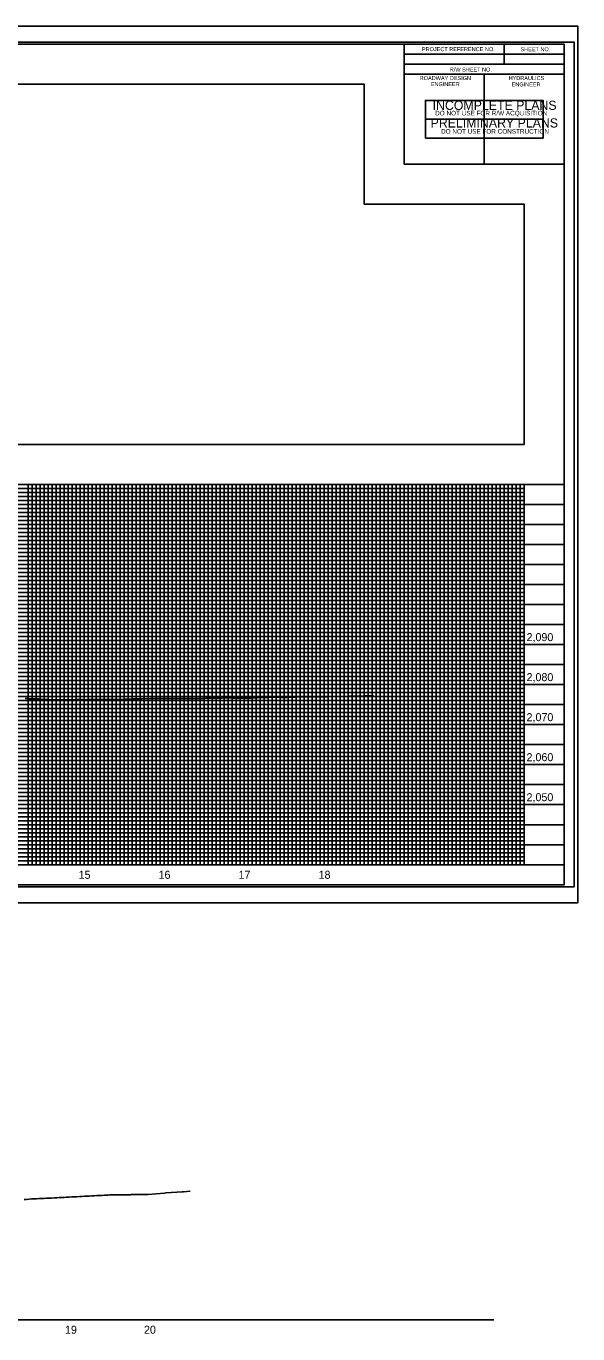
# Model space of a CAD drawing. Extents: x 757145 to 758829, y 592169 to 594973.
# Drawn here: x 758139 to 758829, y 592169 to 593803 of the extents above; entities that cross this region are included whole.
import ezdxf

# ---------------------------------------------------------------- set-up
doc = ezdxf.new("R2010")
doc.units = 0
for name, color, linetype in [('Exist CMT EOP', 7, 'Continuous'), ('Exist Vertical Profile Horizontal Axis Label Major', 7, 'Continuous'), ('Old_Level_63', 7, 'Continuous'), ('Prop CMT DNC', 7, 'Continuous'), ('Prop Dimension', 7, 'Continuous'), ('Scratch_Level_4', 7, 'Continuous'), ('Sheet Cutting Line CELL', 7, 'Continuous'), ('Sheet DOT Grid CELL', 7, 'Continuous'), ('Sheet Plan And Profile CELL', 7, 'Continuous'), ('Sheet Plot Border Inside CELL', 7, 'Continuous'), ('Sheet Plot Border Outside CELL', 7, 'Continuous'), ('Sheet Profile Grid Major CELL', 7, 'Continuous'), ('Sheet Profile Grid Middle CELL', 7, 'Continuous'), ('Sheet Profile Grid Minor CELL', 7, 'Continuous'), ('Sheet Sticker Incomplete CELL', 7, 'Continuous'), ('Sheet Sticker Preliminary CELL', 7, 'Continuous')]:
    doc.layers.add(name, color=color, linetype=linetype)

msp = doc.modelspace()

# ---------------------------------------------------------------- linework, layer by layer
at = {"layer": 'Exist CMT EOP'}
for points in [[(758138.3, 592962.9), (758139.9, 592962.9), (758140.2, 592962.9), (758141.4, 592962.8), (758143, 592962.7), (758144.5, 592962.6), (758146.1, 592962.5), (758147.6, 592962.3), (758149.1, 592962.3), (758150.7, 592962.3), (758152.2, 592962.3), (758153.8, 592962.3), (758154.5, 592962.3), (758155.3, 592962.2), (758156.9, 592962.1), (758158.4, 592961.9), (758160, 592961.8), (758161.5, 592961.7)], [(758161.5, 592961.7), (758161.9, 592961.6), (758163.1, 592961.6), (758164.6, 592961.6), (758165.3, 592961.6), (758166.2, 592961.6), (758167.7, 592961.5), (758169.2, 592961.4), (758170.3, 592961.4), (758170.8, 592961.4), (758172.3, 592961.4), (758173.9, 592961.4), (758175.4, 592961.3), (758177, 592961.3), (758178.5, 592961.3), (758180.1, 592961.3), (758181.6, 592961.3), (758183.2, 592961.3), (758184.7, 592961.3), (758186.3, 592961.3), (758187.8, 592961.3), (758189.3, 592961.3), (758190.9, 592961.3), (758191.8, 592961.3), (758192.4, 592961.3), (758194, 592961.4), (758195.5, 592961.4), (758197.1, 592961.4), (758197.5, 592961.4), (758198.6, 592961.4), (758200.2, 592961.5), (758201.2, 592961.5), (758201.7, 592961.5), (758203.3, 592961.5), (758204.8, 592961.5), (758206.4, 592961.5), (758207.9, 592961.5), (758209.4, 592961.5), (758211, 592961.4), (758212.5, 592961.4), (758214.1, 592961.4), (758214.5, 592961.4), (758215.6, 592961.4), (758217.2, 592961.5), (758218.7, 592961.5), (758219.1, 592961.5), (758220.3, 592961.5), (758221.8, 592961.5), (758223.4, 592961.6), (758224.9, 592961.6), (758226.5, 592961.6), (758228, 592961.6), (758229.5, 592961.6), (758231.1, 592961.6), (758232, 592961.6), (758232.6, 592961.7), (758234.2, 592961.7), (758235.7, 592961.7), (758237.3, 592961.7), (758238.8, 592961.7), (758240.4, 592961.7), (758241.1, 592961.7), (758241.9, 592961.7), (758243.5, 592961.8), (758245, 592961.8), (758246.6, 592961.8), (758250.6, 592961.8), (758263.1, 592962), (758273.2, 592962.4), (758284.2, 592962.4), (758294.6, 592962.8), (758305.3, 592962.8), (758310.5, 592962.9), (758313.4, 592963), (758315.8, 592963), (758316.2, 592963), (758319, 592963), (758321.8, 592962.9), (758324.6, 592962.9), (758326.8, 592962.9), (758327.4, 592962.9), (758330.2, 592962.9), (758333, 592963), (758335.9, 592963), (758337.4, 592963), (758338.7, 592963), (758341.5, 592963), (758344.3, 592962.9), (758347.1, 592962.9), (758348.2, 592962.9), (758349.9, 592962.9), (758352.7, 592963), (758355.5, 592963), (758358.4, 592963.1), (758359.5, 592963.1), (758361.2, 592963.1), (758364, 592963.2), (758366.8, 592963.2), (758369.6, 592963.3), (758370.5, 592963.3), (758372.4, 592963.3)], [(758372.4, 592963.3), (758375.2, 592963.4), (758378.1, 592963.4), (758380.9, 592963.5), (758381.6, 592963.5), (758383.7, 592963.5), (758386.5, 592963.6), (758389.3, 592963.6), (758392.1, 592963.6), (758392.7, 592963.6), (758394.9, 592963.6), (758397.7, 592963.5), (758400.6, 592963.4), (758402.3, 592963.4), (758403.4, 592963.4), (758406.2, 592963.4), (758409, 592963.4), (758411.8, 592963.4), (758412.8, 592963.4), (758414.6, 592963.5), (758417.4, 592963.5), (758419.4, 592963.5), (758420.3, 592963.5), (758423.1, 592963.6), (758425.9, 592963.8), (758428.7, 592963.9), (758431.5, 592964), (758434.3, 592964.1), (758436.4, 592964.2), (758437.1, 592964.2), (758439.9, 592964.2), (758441.3, 592964.3), (758442.8, 592964.3), (758445.6, 592964.4), (758448.4, 592964.4), (758451.2, 592964.5), (758454, 592964.4), (758456.8, 592964.3), (758459.3, 592964.2), (758459.6, 592964.2), (758462.4, 592964.3), (758465.3, 592964.3), (758468.1, 592964.4), (758469.7, 592964.4), (758470.9, 592964.5), (758473.7, 592964.6), (758476.5, 592964.7), (758479.3, 592964.8), (758481.7, 592964.9), (758482.1, 592964.9), (758485, 592964.9), (758487.8, 592964.9), (758490.6, 592964.8), (758493.6, 592964.8), (758496.2, 592964.9), (758499, 592964.9), (758501.8, 592965), (758503.3, 592965), (758504.6, 592965), (758507.5, 592965), (758510.3, 592965.1), (758515.6, 592965.1), (758524.8, 592965.3), (758529.3, 592965.3), (758542.9, 592965.8), (758549.7, 592965.8), (758562.9, 592966.3), (758570, 592966.3), (758573.7, 592966.5)], [(758136.8, 592337), (758139.9, 592337.2), (758143, 592337.5), (758146.2, 592337.7), (758148.2, 592337.8), (758148.7, 592337.8), (758149.3, 592337.9), (758152.5, 592338), (758155.6, 592338.2), (758158.7, 592338.3), (758161.9, 592338.5), (758165, 592338.6), (758168.2, 592338.8), (758168.9, 592338.8), (758169.6, 592338.8), (758171.3, 592338.9), (758174.4, 592339.1), (758177.6, 592339.2), (758180.7, 592339.4), (758183.9, 592339.5), (758187, 592339.7), (758189.5, 592339.8), (758190.2, 592339.8), (758193.3, 592340)], [(758193.3, 592340), (758196.4, 592340.2), (758199.6, 592340.4), (758202.7, 592340.5), (758205.9, 592340.7), (758209, 592340.9), (758212.2, 592341.1), (758215.3, 592341.2), (758218.4, 592341.4), (758221.6, 592341.6), (758224.7, 592341.7), (758227.8, 592341.9), (758231, 592342.1), (758234.3, 592342.2), (758237.3, 592342.4), (758240.4, 592342.6), (758241.7, 592342.6), (758243.5, 592342.7), (758246.7, 592342.8), (758249.1, 592342.9), (758249.8, 592342.9), (758253, 592342.9), (758256.1, 592343), (758259.2, 592343), (758262.4, 592343.1), (758265.5, 592343.1), (758269.5, 592343.1), (758270.6, 592343.2), (758290.7, 592343.4), (758291.4, 592343.4), (758312.3, 592345.1), (758313.8, 592345.2), (758334.5, 592346.7), (758336.2, 592346.8), (758344.3, 592347.3)]]:
    msp.add_lwpolyline(points, dxfattribs=at)
at = {"layer": 'Exist Vertical Profile Horizontal Axis Label Major'}
msp.add_lwpolyline([(757361.9, 593280.3), (757361.9, 593730.3), (758561.9, 593730.3), (758561.9, 593580.3), (758761.9, 593580.3), (758761.9, 593280.3)], close=True, dxfattribs=at)
at = {"layer": 'Prop Dimension'}
msp.add_lwpolyline([(757361.9, 593230.3), (758761.9, 593230.3), (758761.9, 592755.3), (757361.9, 592755.3)], close=True, dxfattribs=at)
at = {"layer": 'Scratch_Level_4'}
for p, q in [((757711.9, 592830.3), (758636.9, 592830.3)), ((757294.3, 592186.9), (758724, 592186.9))]:
    msp.add_line(p, q, dxfattribs=at)
at = {"layer": 'Sheet Cutting Line CELL'}
for p, q in [((758828.9, 593802.8), (757145.4, 593802.8)), ((757145.4, 592707.8), (758828.9, 592707.8))]:
    msp.add_line(p, q, dxfattribs=at)
at = {"layer": 'Sheet DOT Grid CELL'}
for p, q in [((757311.9, 593230.3), (758811.9, 593230.3)), ((758161.9, 593230.3), (758161.9, 592755.3)), ((758211.9, 593230.3), (758211.9, 592755.3)), ((758261.9, 593230.3), (758261.9, 592755.3)), ((758311.9, 593230.3), (758311.9, 592755.3)), ((758361.9, 593230.3), (758361.9, 592755.3)), ((758411.9, 593230.3), (758411.9, 592755.3)), ((758461.9, 593230.3), (758461.9, 592755.3)), ((758511.9, 593230.3), (758511.9, 592755.3)), ((758561.9, 593230.3), (758561.9, 592755.3)), ((758611.9, 593230.3), (758611.9, 592755.3)), ((758661.9, 593230.3), (758661.9, 592755.3)), ((758711.9, 593230.3), (758711.9, 592755.3)), ((758761.9, 593230.3), (758761.9, 592755.3)), ((757311.9, 593180.3), (758811.9, 593180.3)), ((757311.9, 593130.3), (758811.9, 593130.3)), ((757311.9, 593080.3), (758811.9, 593080.3)), ((757311.9, 593030.3), (758811.9, 593030.3)), ((757311.9, 592980.3), (758811.9, 592980.3)), ((757311.9, 592930.3), (758811.9, 592930.3)), ((757311.9, 592880.3), (758811.9, 592880.3)), ((757311.9, 592830.3), (758811.9, 592830.3)), ((757311.9, 592780.3), (758811.9, 592780.3))]:
    msp.add_line(p, q, dxfattribs=at)
at = {"layer": 'Sheet Plan And Profile CELL'}
for p, q in [((758736.9, 593780.3), (758736.9, 593755.3)), ((758611.9, 593767.8), (758811.9, 593767.8)), ((758611.9, 593755.3), (758811.9, 593755.3)), ((758611.9, 593755.3), (758611.9, 593742.8)), ((758711.9, 593742.8), (758711.9, 593630.3)), ((758811.9, 592755.3), (757311.9, 592755.3))]:
    msp.add_line(p, q, dxfattribs=at)
for points in [[(758811.9, 593780.3), (757311.9, 593780.3), (757311.9, 592730.3), (758811.9, 592730.3)], [(758611.9, 593780.3), (758811.9, 593780.3), (758811.9, 593755.3), (758611.9, 593755.3)], [(758611.9, 593742.8), (758711.9, 593742.8), (758711.9, 593630.3), (758611.9, 593630.3)], [(758711.9, 593742.8), (758811.9, 593742.8), (758811.9, 593630.3), (758711.9, 593630.3)]]:
    msp.add_lwpolyline(points, close=True, dxfattribs=at)
at = {"layer": 'Sheet Plot Border Inside CELL'}
msp.add_lwpolyline([(757158.4, 592727.8), (758824.4, 592727.8), (758824.4, 593782.8), (757158.4, 593782.8)], close=True, dxfattribs=at)
at = {"layer": 'Sheet Plot Border Outside CELL'}
msp.add_lwpolyline([(757145.4, 592707.8), (758828.9, 592707.8), (758828.9, 593802.8), (757145.4, 593802.8)], close=True, dxfattribs=at)
at = {"layer": 'Sheet Profile Grid Major CELL'}
for points in [[(757311.9, 593230.3), (758811.9, 593230.3)], [(758161.9, 592755.3), (758161.9, 593230.3), (758211.9, 593230.3), (758211.9, 592755.3)], [(758261.9, 592755.3), (758261.9, 593230.3), (758311.9, 593230.3), (758311.9, 592755.3)], [(758361.9, 592755.3), (758361.9, 593230.3), (758411.9, 593230.3), (758411.9, 592755.3)], [(758461.9, 592755.3), (758461.9, 593230.3), (758511.9, 593230.3), (758511.9, 592755.3)], [(758561.9, 592755.3), (758561.9, 593230.3), (758611.9, 593230.3), (758611.9, 592755.3)], [(758661.9, 592755.3), (758661.9, 593230.3), (758711.9, 593230.3), (758711.9, 592755.3)], [(758761.9, 592755.3), (758761.9, 593230.3)], [(758811.9, 593180.3), (757311.9, 593180.3), (757311.9, 593130.3), (758811.9, 593130.3)], [(758811.9, 593080.3), (757311.9, 593080.3), (757311.9, 593030.3), (758811.9, 593030.3)], [(758811.9, 592980.3), (757311.9, 592980.3), (757311.9, 592930.3), (758811.9, 592930.3)], [(758811.9, 592880.3), (757311.9, 592880.3), (757311.9, 592830.3), (758811.9, 592830.3)], [(758811.9, 592780.3), (757311.9, 592780.3)]]:
    msp.add_lwpolyline(points, dxfattribs=at)
at = {"layer": 'Sheet Profile Grid Middle CELL'}
for p, q in [((757311.9, 593205.3), (758811.9, 593205.3)), ((758811.9, 593155.3), (757311.9, 593155.3)), ((757311.9, 593105.3), (758811.9, 593105.3)), ((758811.9, 593055.3), (757311.9, 593055.3)), ((757311.9, 593005.3), (758811.9, 593005.3)), ((758811.9, 592955.3), (757311.9, 592955.3)), ((757311.9, 592905.3), (758811.9, 592905.3)), ((758811.9, 592855.3), (757311.9, 592855.3)), ((757311.9, 592805.3), (758811.9, 592805.3))]:
    msp.add_line(p, q, dxfattribs=at)
for points in [[(758186.9, 592755.3), (758186.9, 593230.3), (758236.9, 593230.3), (758236.9, 592755.3)], [(758286.9, 592755.3), (758286.9, 593230.3), (758336.9, 593230.3), (758336.9, 592755.3)], [(758386.9, 592755.3), (758386.9, 593230.3), (758436.9, 593230.3), (758436.9, 592755.3)], [(758486.9, 592755.3), (758486.9, 593230.3), (758536.9, 593230.3), (758536.9, 592755.3)], [(758586.9, 592755.3), (758586.9, 593230.3), (758636.9, 593230.3), (758636.9, 592755.3)], [(758686.9, 592755.3), (758686.9, 593230.3), (758736.9, 593230.3), (758736.9, 592755.3)]]:
    msp.add_lwpolyline(points, dxfattribs=at)
at = {"layer": 'Sheet Profile Grid Minor CELL'}
for points in [[(757361.9, 593220.3), (758761.9, 593220.3), (758761.9, 593225.3), (757361.9, 593225.3)], [(758141.9, 592755.3), (758141.9, 593230.3), (758146.9, 593230.3), (758146.9, 592755.3)], [(758151.9, 592755.3), (758151.9, 593230.3), (758156.9, 593230.3), (758156.9, 592755.3)], [(758166.9, 592755.3), (758166.9, 593230.3), (758171.9, 593230.3), (758171.9, 592755.3)], [(758176.9, 592755.3), (758176.9, 593230.3), (758181.9, 593230.3), (758181.9, 592755.3)], [(758191.9, 592755.3), (758191.9, 593230.3), (758196.9, 593230.3), (758196.9, 592755.3)], [(758201.9, 592755.3), (758201.9, 593230.3), (758206.9, 593230.3), (758206.9, 592755.3)], [(758216.9, 592755.3), (758216.9, 593230.3), (758221.9, 593230.3), (758221.9, 592755.3)], [(758226.9, 592755.3), (758226.9, 593230.3), (758231.9, 593230.3), (758231.9, 592755.3)], [(758241.9, 592755.3), (758241.9, 593230.3), (758246.9, 593230.3), (758246.9, 592755.3)], [(758251.9, 592755.3), (758251.9, 593230.3), (758256.9, 593230.3), (758256.9, 592755.3)], [(758266.9, 592755.3), (758266.9, 593230.3), (758271.9, 593230.3), (758271.9, 592755.3)], [(758276.9, 592755.3), (758276.9, 593230.3), (758281.9, 593230.3), (758281.9, 592755.3)], [(758291.9, 592755.3), (758291.9, 593230.3), (758296.9, 593230.3), (758296.9, 592755.3)], [(758301.9, 592755.3), (758301.9, 593230.3), (758306.9, 593230.3), (758306.9, 592755.3)], [(758316.9, 592755.3), (758316.9, 593230.3), (758321.9, 593230.3), (758321.9, 592755.3)], [(758326.9, 592755.3), (758326.9, 593230.3), (758331.9, 593230.3), (758331.9, 592755.3)], [(758341.9, 592755.3), (758341.9, 593230.3), (758346.9, 593230.3), (758346.9, 592755.3)], [(758351.9, 592755.3), (758351.9, 593230.3), (758356.9, 593230.3), (758356.9, 592755.3)], [(758366.9, 592755.3), (758366.9, 593230.3), (758371.9, 593230.3), (758371.9, 592755.3)], [(758376.9, 592755.3), (758376.9, 593230.3), (758381.9, 593230.3), (758381.9, 592755.3)], [(758391.9, 592755.3), (758391.9, 593230.3), (758396.9, 593230.3), (758396.9, 592755.3)], [(758401.9, 592755.3), (758401.9, 593230.3), (758406.9, 593230.3), (758406.9, 592755.3)], [(758416.9, 592755.3), (758416.9, 593230.3), (758421.9, 593230.3), (758421.9, 592755.3)], [(758426.9, 592755.3), (758426.9, 593230.3), (758431.9, 593230.3), (758431.9, 592755.3)], [(758441.9, 592755.3), (758441.9, 593230.3), (758446.9, 593230.3), (758446.9, 592755.3)], [(758451.9, 592755.3), (758451.9, 593230.3), (758456.9, 593230.3), (758456.9, 592755.3)], [(758466.9, 592755.3), (758466.9, 593230.3), (758471.9, 593230.3), (758471.9, 592755.3)], [(758476.9, 592755.3), (758476.9, 593230.3), (758481.9, 593230.3), (758481.9, 592755.3)], [(758491.9, 592755.3), (758491.9, 593230.3), (758496.9, 593230.3), (758496.9, 592755.3)], [(758501.9, 592755.3), (758501.9, 593230.3), (758506.9, 593230.3), (758506.9, 592755.3)], [(758516.9, 592755.3), (758516.9, 593230.3), (758521.9, 593230.3), (758521.9, 592755.3)], [(758526.9, 592755.3), (758526.9, 593230.3), (758531.9, 593230.3), (758531.9, 592755.3)], [(758541.9, 592755.3), (758541.9, 593230.3), (758546.9, 593230.3), (758546.9, 592755.3)], [(758551.9, 592755.3), (758551.9, 593230.3), (758556.9, 593230.3), (758556.9, 592755.3)], [(758566.9, 592755.3), (758566.9, 593230.3), (758571.9, 593230.3), (758571.9, 592755.3)], [(758576.9, 592755.3), (758576.9, 593230.3), (758581.9, 593230.3), (758581.9, 592755.3)], [(758591.9, 592755.3), (758591.9, 593230.3), (758596.9, 593230.3), (758596.9, 592755.3)], [(758601.9, 592755.3), (758601.9, 593230.3), (758606.9, 593230.3), (758606.9, 592755.3)], [(758616.9, 592755.3), (758616.9, 593230.3), (758621.9, 593230.3), (758621.9, 592755.3)], [(758626.9, 592755.3), (758626.9, 593230.3), (758631.9, 593230.3), (758631.9, 592755.3)], [(758641.9, 592755.3), (758641.9, 593230.3), (758646.9, 593230.3), (758646.9, 592755.3)], [(758651.9, 592755.3), (758651.9, 593230.3), (758656.9, 593230.3), (758656.9, 592755.3)], [(758666.9, 592755.3), (758666.9, 593230.3), (758671.9, 593230.3), (758671.9, 592755.3)], [(758676.9, 592755.3), (758676.9, 593230.3), (758681.9, 593230.3), (758681.9, 592755.3)], [(758691.9, 592755.3), (758691.9, 593230.3), (758696.9, 593230.3), (758696.9, 592755.3)], [(758701.9, 592755.3), (758701.9, 593230.3), (758706.9, 593230.3), (758706.9, 592755.3)], [(758716.9, 592755.3), (758716.9, 593230.3), (758721.9, 593230.3), (758721.9, 592755.3)], [(758726.9, 592755.3), (758726.9, 593230.3), (758731.9, 593230.3), (758731.9, 592755.3)], [(758741.9, 592755.3), (758741.9, 593230.3), (758746.9, 593230.3), (758746.9, 592755.3)], [(758751.9, 592755.3), (758751.9, 593230.3), (758756.9, 593230.3), (758756.9, 592755.3)], [(757361.9, 593210.3), (758761.9, 593210.3), (758761.9, 593215.3), (757361.9, 593215.3)], [(757361.9, 593195.3), (758761.9, 593195.3), (758761.9, 593200.3), (757361.9, 593200.3)], [(757361.9, 593185.3), (758761.9, 593185.3), (758761.9, 593190.3), (757361.9, 593190.3)], [(757361.9, 593170.3), (758761.9, 593170.3), (758761.9, 593175.3), (757361.9, 593175.3)], [(757361.9, 593160.3), (758761.9, 593160.3), (758761.9, 593165.3), (757361.9, 593165.3)], [(757361.9, 593145.3), (758761.9, 593145.3), (758761.9, 593150.3), (757361.9, 593150.3)], [(757361.9, 593135.3), (758761.9, 593135.3), (758761.9, 593140.3), (757361.9, 593140.3)], [(757361.9, 593125.3), (758761.9, 593125.3)], [(757361.9, 593115.3), (758761.9, 593115.3), (758761.9, 593120.3), (757361.9, 593120.3)], [(757361.9, 593100.3), (758761.9, 593100.3), (758761.9, 593110.3), (757361.9, 593110.3)], [(757361.9, 593090.3), (758761.9, 593090.3), (758761.9, 593095.3), (757361.9, 593095.3)], [(757361.9, 593075.3), (758761.9, 593075.3), (758761.9, 593085.3), (757361.9, 593085.3)], [(757361.9, 593065.3), (758761.9, 593065.3), (758761.9, 593070.3), (757361.9, 593070.3)], [(757361.9, 593050.3), (758761.9, 593050.3), (758761.9, 593060.3), (757361.9, 593060.3)], [(757361.9, 593040.3), (758761.9, 593040.3), (758761.9, 593045.3), (757361.9, 593045.3)], [(757361.9, 593025.3), (758761.9, 593025.3), (758761.9, 593035.3), (757361.9, 593035.3)], [(757361.9, 593015.3), (758761.9, 593015.3), (758761.9, 593020.3), (757361.9, 593020.3)], [(757361.9, 593000.3), (758761.9, 593000.3), (758761.9, 593010.3), (757361.9, 593010.3)], [(757361.9, 592990.3), (758761.9, 592990.3), (758761.9, 592995.3), (757361.9, 592995.3)], [(757361.9, 592975.3), (758761.9, 592975.3), (758761.9, 592985.3), (757361.9, 592985.3)], [(757361.9, 592965.3), (758761.9, 592965.3), (758761.9, 592970.3), (757361.9, 592970.3)], [(757361.9, 592950.3), (758761.9, 592950.3), (758761.9, 592960.3), (757361.9, 592960.3)], [(757361.9, 592940.3), (758761.9, 592940.3), (758761.9, 592945.3), (757361.9, 592945.3)], [(757361.9, 592925.3), (758761.9, 592925.3), (758761.9, 592935.3), (757361.9, 592935.3)], [(757361.9, 592915.3), (758761.9, 592915.3), (758761.9, 592920.3), (757361.9, 592920.3)], [(757361.9, 592900.3), (758761.9, 592900.3), (758761.9, 592910.3), (757361.9, 592910.3)], [(757361.9, 592890.3), (758761.9, 592890.3), (758761.9, 592895.3), (757361.9, 592895.3)], [(757361.9, 592875.3), (758761.9, 592875.3), (758761.9, 592885.3), (757361.9, 592885.3)], [(757361.9, 592865.3), (758761.9, 592865.3), (758761.9, 592870.3), (757361.9, 592870.3)], [(757361.9, 592850.3), (758761.9, 592850.3), (758761.9, 592860.3), (757361.9, 592860.3)], [(757361.9, 592840.3), (758761.9, 592840.3), (758761.9, 592845.3), (757361.9, 592845.3)], [(757361.9, 592825.3), (758761.9, 592825.3), (758761.9, 592835.3), (757361.9, 592835.3)], [(757361.9, 592760.3), (758761.9, 592760.3), (758761.9, 592765.3), (757361.9, 592765.3), (757361.9, 592770.3), (758761.9, 592770.3), (758761.9, 592775.3), (757361.9, 592775.3), (757361.9, 592780.3), (757361.9, 592785.3), (758761.9, 592785.3), (758761.9, 592790.3), (757361.9, 592790.3), (757361.9, 592795.3), (758761.9, 592795.3), (758761.9, 592800.3), (757361.9, 592800.3), (757361.9, 592805.3), (757361.9, 592810.3), (758761.9, 592810.3), (758761.9, 592815.3), (757361.9, 592815.3), (757361.9, 592820.3), (758761.9, 592820.3)]]:
    msp.add_lwpolyline(points, dxfattribs=at)
at = {"layer": 'Sheet Sticker Incomplete CELL'}
msp.add_lwpolyline([(758638.4, 593686.5), (758638.4, 593710), (758785.4, 593710), (758785.4, 593686.5)], close=True, dxfattribs=at)
at = {"layer": 'Sheet Sticker Preliminary CELL'}
msp.add_lwpolyline([(758638.4, 593663), (758638.4, 593686.5), (758785.4, 593686.5), (758785.4, 593663)], close=True, dxfattribs=at)

# ---------------------------------------------------------------- texts
at = {"layer": 'Old_Level_63'}
for s, p in [('2,090', (758764.8, 593034.6)), ('2,080', (758764.8, 592984.6)), ('2,070', (758764.8, 592934.6)), ('2,060', (758764.8, 592884.6)), ('2,050', (758764.8, 592834.6))]:
    msp.add_text(s, height=10, dxfattribs=at).set_placement(p)
at = {"layer": 'Prop CMT DNC'}
for s, p in [('16', (758304.9, 592737.7)), ('18', (758504.9, 592737.7)), ('15', (758205, 592737.7)), ('17', (758404.8, 592737.7)), ('19', (758188, 592169.4)), ('20', (758286.7, 592169.4))]:
    msp.add_text(s, height=10, dxfattribs=at).set_placement(p)
at = {"layer": 'Sheet Plan And Profile CELL'}
for s, p in [('PROJECT REFERENCE NO.', (758634.1, 593771.6)), ('SHEET NO.', (758757.2, 593771.5)), ('R/W SHEET NO.', (758668.9, 593746.1)), ('ROADWAY DESIGN', (758631.3, 593735.5)), ('ENGINEER', (758645.2, 593727.9)), ('HYDRAULICS', (758742.4, 593735.5)), ('ENGINEER', (758746.2, 593727.5))]:
    msp.add_text(s, height=5, dxfattribs=at).set_placement(p)
at = {"layer": 'Sheet Sticker Incomplete CELL'}
for s, height, p in [('INCOMPLETE PLANS', 11.52, (758647.4, 593698.2)), ('DO NOT USE FOR R/W ACQUISITION', 5.76, (758650.6, 593691.3))]:
    msp.add_text(s, height=height, dxfattribs=at).set_placement(p)
at = {"layer": 'Sheet Sticker Preliminary CELL'}
for s, height, p in [('PRELIMINARY PLANS', 11.52, (758644.9, 593676.2)), ('DO NOT USE FOR CONSTRUCTION', 5.76, (758658, 593668.5))]:
    msp.add_text(s, height=height, dxfattribs=at).set_placement(p)

doc.saveas('drawing.dxf')
